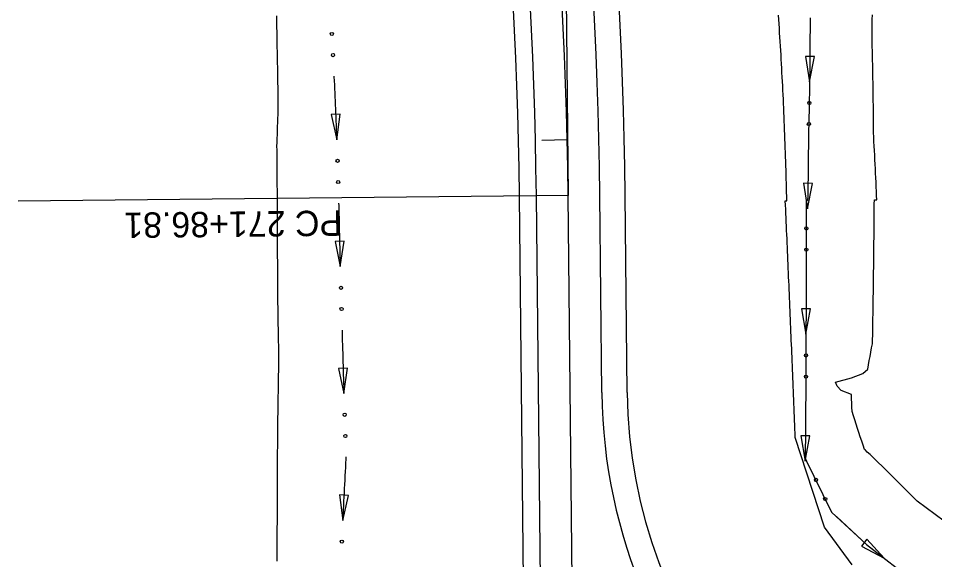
# Model space of a CAD drawing. Extents: x 1611108 to 1749517, y 619561 to 797725.
# Drawn here: x 1713886.8 to 1714103.5, y 759365.7 to 759493.8 of the extents above; entities that cross this region are included whole.
import ezdxf

# ---------------------------------------------------------------- set-up
doc = ezdxf.new("R2010")
doc.units = 0
for name, color, linetype in [('R_Ditch', 7, 'Continuous'), ('R_Horz Alg', 7, 'Continuous'), ('R_Horz Alg Annot', 7, 'Continuous'), ('R_Horz Alg Stationing', 7, 'Continuous'), ('R_Proposed Const Limits', 7, 'Continuous'), ('R_Proposed Road', 7, 'Continuous'), ('R_Proposed_SHLDR', 7, 'Continuous')]:
    doc.layers.add(name, color=color, linetype=linetype)

msp = doc.modelspace()

# ---------------------------------------------------------------- linework, layer by layer
at = {"layer": 'R_Ditch'}
for p, q in [((1714075.03, 759484.75), (1714072.91, 759484.77)), ((1714072.91, 759484.77), (1714073.9, 759478.76)), ((1714073.9, 759478.76), (1714075.03, 759484.75)), ((1713962.91, 759471.09), (1713960.8, 759471.01)), ((1713960.8, 759471.01), (1713962.09, 759465.05)), ((1713962.09, 759465.05), (1713962.91, 759471.09)), ((1714074.57, 759454.71), (1714072.46, 759454.75)), ((1714072.46, 759454.75), (1714073.39, 759448.73)), ((1714073.39, 759448.73), (1714074.57, 759454.71)), ((1713963.82, 759441.05), (1713961.71, 759441)), ((1713961.71, 759441), (1713962.92, 759435.03)), ((1713962.92, 759435.03), (1713963.82, 759441.05)), ((1714074.11, 759425.03), (1714072, 759425.04)), ((1714072, 759425.04), (1714073.04, 759419.04)), ((1714073.04, 759419.04), (1714074.11, 759425.03)), ((1713964.66, 759411.03), (1713962.54, 759410.97)), ((1713962.54, 759410.97), (1713963.78, 759405)), ((1713963.78, 759405), (1713964.66, 759411.03)), ((1714073.97, 759394.99), (1714071.85, 759395.01)), ((1714071.85, 759395.01), (1714072.87, 759389)), ((1714072.87, 759389), (1714073.97, 759394.99)), ((1713964.85, 759380.94), (1713962.74, 759381.04)), ((1713962.74, 759381.04), (1713963.5, 759375)), ((1713963.5, 759375), (1713964.85, 759380.94)), ((1714087.47, 759370.6), (1714086.17, 759368.93)), ((1714091.56, 759366.08), (1714087.47, 759370.6)), ((1714086.17, 759368.93), (1714091.56, 759366.08))]:
    msp.add_line(p, q, dxfattribs=at)
for points in [[(1714084, 759364.54), (1714077.44, 759373.4), (1714070.49, 759394.62), (1714070.45, 759395.62), (1714070.41, 759396.62), (1714070.37, 759397.62), (1714070.33, 759398.62), (1714070.3, 759399.62), (1714070.26, 759400.62), (1714070.22, 759401.62), (1714070.18, 759402.62), (1714070.14, 759403.62), (1714070.1, 759404.62), (1714070.06, 759405.62), (1714070.02, 759406.62), (1714069.99, 759407.62), (1714069.95, 759408.62), (1714069.91, 759409.62), (1714069.87, 759410.62), (1714069.83, 759411.62), (1714069.79, 759412.62), (1714069.75, 759413.62), (1714069.71, 759414.62), (1714069.66, 759415.62), (1714069.62, 759416.61), (1714069.58, 759417.61), (1714069.54, 759418.61), (1714069.5, 759419.61), (1714069.46, 759420.61), (1714069.42, 759421.61), (1714069.38, 759422.61), (1714069.34, 759423.61), (1714069.29, 759424.61), (1714069.25, 759425.61), (1714069.21, 759426.61), (1714069.17, 759427.61), (1714069.13, 759428.61), (1714069.08, 759429.61), (1714069.04, 759430.61), (1714069, 759431.61), (1714068.95, 759432.61), (1714068.91, 759433.61), (1714068.87, 759434.61), (1714068.82, 759435.61), (1714068.78, 759436.61), (1714068.74, 759437.61), (1714068.69, 759438.61), (1714068.65, 759439.61), (1714068.61, 759440.61), (1714068.56, 759441.61), (1714068.52, 759442.6), (1714068.47, 759443.6), (1714068.43, 759444.6), (1714068.38, 759445.6), (1714068.34, 759446.6), (1714068.29, 759447.6), (1714068.25, 759448.6), (1714068.2, 759449.6), (1714068.16, 759450.6), (1714068.16, 759450.61), (1714068.51, 759450.63), (1714068.49, 759451.61), (1714068.47, 759452.61), (1714068.44, 759453.66), (1714068.41, 759454.71), (1714068.39, 759455.76), (1714068.36, 759456.81), (1714068.33, 759457.86), (1714068.3, 759458.91), (1714068.26, 759459.96), (1714068.23, 759461.01), (1714068.2, 759462.06), (1714068.16, 759463.11), (1714068.12, 759464.15), (1714068.08, 759465.2), (1714068.04, 759466.25), (1714068, 759467.3), (1714067.96, 759468.35), (1714067.92, 759469.4), (1714067.88, 759470.45), (1714067.83, 759471.5), (1714067.78, 759472.54), (1714067.74, 759473.59), (1714067.69, 759474.64), (1714067.64, 759475.69), (1714067.59, 759476.74), (1714067.54, 759477.79), (1714067.48, 759478.83), (1714067.43, 759479.88), (1714067.37, 759480.93), (1714067.32, 759481.98), (1714067.26, 759483.02), (1714067.2, 759484.07), (1714067.14, 759485.12), (1714067.08, 759486.17), (1714067.02, 759487.21), (1714066.95, 759488.26), (1714066.89, 759489.31), (1714066.82, 759490.36), (1714066.75, 759491.4), (1714066.69, 759492.45), (1714066.62, 759493.5), (1714066.55, 759494.54)], [(1714074, 759493.85), (1714074, 759492.79), (1714074, 759491.74), (1714074, 759490.68), (1714073.99, 759489.62), (1714073.99, 759488.57), (1714073.98, 759487.51), (1714073.98, 759486.45), (1714073.97, 759485.4), (1714073.96, 759484.34), (1714073.95, 759483.28), (1714073.94, 759482.22), (1714073.93, 759481.17), (1714073.91, 759480.11), (1714073.9, 759479.05), (1714073.88, 759478), (1714073.86, 759476.94), (1714073.85, 759475.89), (1714073.83, 759474.83), (1714073.81, 759473.77), (1714073.78, 759472.72), (1714073.76, 759471.66), (1714073.74, 759470.6), (1714073.71, 759469.55), (1714073.68, 759468.49), (1714073.66, 759467.44), (1714073.63, 759466.38), (1714073.62, 759465.33), (1714073.62, 759464.27), (1714073.61, 759463.22), (1714073.6, 759462.16), (1714073.59, 759461.11), (1714073.58, 759460.05), (1714073.57, 759459), (1714073.56, 759457.94), (1714073.54, 759456.89), (1714073.53, 759455.83), (1714073.51, 759454.78), (1714073.49, 759453.72), (1714073.47, 759452.67), (1714073.45, 759451.66), (1714073.43, 759450.68), (1714073.07, 759450.66), (1714073.07, 759450.65), (1714073.07, 759449.65), (1714073.07, 759448.65), (1714073.08, 759447.65), (1714073.08, 759446.65), (1714073.08, 759445.65), (1714073.08, 759444.65), (1714073.08, 759443.65), (1714073.08, 759442.65), (1714073.08, 759441.65), (1714073.08, 759440.65), (1714073.08, 759439.65), (1714073.08, 759438.65), (1714073.08, 759437.65), (1714073.07, 759436.65), (1714073.07, 759435.65), (1714073.07, 759434.65), (1714073.07, 759433.65), (1714073.07, 759432.65), (1714073.07, 759431.65), (1714073.07, 759430.65), (1714073.06, 759429.65), (1714073.06, 759428.65), (1714073.06, 759427.65), (1714073.06, 759426.65), (1714073.06, 759425.65), (1714073.05, 759424.65), (1714073.05, 759423.65), (1714073.05, 759422.65), (1714073.04, 759421.65), (1714073.04, 759420.65), (1714073.04, 759419.65), (1714073.03, 759418.65), (1714073.03, 759417.65), (1714073.03, 759416.65), (1714073.02, 759415.65), (1714073.02, 759414.65), (1714073.02, 759413.65), (1714073.01, 759412.65), (1714073.01, 759411.65), (1714073, 759410.65), (1714073, 759409.65), (1714072.99, 759408.65), (1714072.99, 759407.65), (1714072.98, 759406.65), (1714072.98, 759405.65), (1714072.97, 759404.65), (1714072.97, 759403.65), (1714072.96, 759402.65), (1714072.95, 759401.65), (1714072.95, 759400.65), (1714072.94, 759399.65), (1714072.94, 759398.65), (1714072.93, 759397.65), (1714072.92, 759396.65), (1714072.92, 759395.65), (1714072.91, 759394.65), (1714072.9, 759393.65), (1714072.89, 759392.65), (1714072.89, 759391.65), (1714072.88, 759390.65), (1714072.87, 759389.65), (1714079.11, 759376.95), (1714087.36, 759369.35), (1714098.95, 759360.33)], [(1714074, 759493.76), (1714074, 759492.79), (1714074, 759491.74), (1714074, 759490.68), (1714073.99, 759489.62), (1714073.99, 759488.57), (1714073.98, 759487.51), (1714073.98, 759486.45), (1714073.97, 759485.4), (1714073.96, 759484.34), (1714073.95, 759483.28), (1714073.94, 759482.22), (1714073.93, 759481.17), (1714073.91, 759480.11), (1714073.9, 759479.05), (1714073.89, 759478.76)], [(1713961.44, 759480.08), (1713961.44, 759480.04)], [(1713961.44, 759480.04), (1713961.44, 759479.91), (1713961.49, 759478.97), (1713961.54, 759478.02), (1713961.58, 759477.07), (1713961.63, 759476.13), (1713961.67, 759475.18), (1713961.71, 759474.23), (1713961.75, 759473.29), (1713961.79, 759472.34), (1713961.83, 759471.39), (1713961.87, 759470.45), (1713961.91, 759469.5), (1713961.95, 759468.55), (1713961.99, 759467.61), (1713962.02, 759466.66), (1713962.06, 759465.71), (1713962.08, 759465.05)], [(1714073.61, 759463.73), (1714073.61, 759463.22), (1714073.6, 759462.16), (1714073.59, 759461.11), (1714073.58, 759460.05), (1714073.57, 759459), (1714073.56, 759457.94), (1714073.54, 759456.89), (1714073.53, 759455.83), (1714073.51, 759454.78), (1714073.49, 759453.72), (1714073.47, 759452.67), (1714073.45, 759451.66), (1714073.43, 759450.68), (1714073.07, 759450.66), (1714073.07, 759450.65), (1714073.07, 759449.65), (1714073.07, 759449.07)], [(1714073.61, 759463.76), (1714073.61, 759463.73)], [(1713962.54, 759450.06), (1713962.54, 759450.02)], [(1713962.54, 759450.02), (1713962.55, 759449.51), (1713962.58, 759448.51), (1713962.6, 759447.51), (1713962.63, 759446.51), (1713962.65, 759445.51), (1713962.68, 759444.51), (1713962.7, 759443.51), (1713962.73, 759442.51), (1713962.75, 759441.51), (1713962.78, 759440.51), (1713962.8, 759439.51), (1713962.83, 759438.51), (1713962.86, 759437.51), (1713962.88, 759436.51), (1713962.91, 759435.51), (1713962.92, 759435.03)], [(1714073.07, 759434.04), (1714073.07, 759433.65), (1714073.07, 759432.65), (1714073.07, 759431.65), (1714073.07, 759430.65), (1714073.06, 759429.65), (1714073.06, 759428.65), (1714073.06, 759427.65), (1714073.06, 759426.65), (1714073.06, 759425.65), (1714073.05, 759424.65), (1714073.05, 759423.65), (1714073.05, 759422.65), (1714073.04, 759421.65), (1714073.04, 759420.65), (1714073.04, 759419.65), (1714073.04, 759419.04)], [(1714073.07, 759434.07), (1714073.07, 759434.04)], [(1713963.34, 759420.03), (1713963.34, 759420)], [(1713963.34, 759419.99), (1713963.35, 759419.52), (1713963.38, 759418.52), (1713963.41, 759417.52), (1713963.44, 759416.52), (1713963.47, 759415.52), (1713963.5, 759414.52), (1713963.53, 759413.52), (1713963.56, 759412.52), (1713963.59, 759411.52), (1713963.62, 759410.52), (1713963.65, 759409.52), (1713963.68, 759408.52), (1713963.71, 759407.52), (1713963.74, 759406.52), (1713963.77, 759405.52), (1713963.78, 759405)], [(1714072.97, 759404), (1714072.97, 759403.65), (1714072.96, 759402.65), (1714072.95, 759401.65), (1714072.95, 759400.65), (1714072.94, 759399.65), (1714072.94, 759398.65), (1714072.93, 759397.65), (1714072.92, 759396.65), (1714072.92, 759395.65), (1714072.91, 759394.65), (1714072.9, 759393.65), (1714072.89, 759392.65), (1714072.89, 759391.65), (1714072.88, 759390.65), (1714072.87, 759389.65), (1714073.16, 759389.07)], [(1714072.97, 759404.04), (1714072.97, 759404)], [(1713964.25, 759389.98), (1713964.23, 759389.53), (1713964.18, 759388.53), (1713964.13, 759387.54), (1713964.08, 759386.54), (1713964.03, 759385.54), (1713963.98, 759384.54), (1713963.93, 759383.54), (1713963.87, 759382.54), (1713963.82, 759381.54), (1713963.77, 759380.54), (1713963.72, 759379.54), (1713963.68, 759378.54), (1713963.63, 759377.55), (1713963.58, 759376.55), (1713963.53, 759375.55), (1713963.5, 759375)], [(1713964.25, 759390.02), (1713964.25, 759389.98)], [(1714080.21, 759375.93), (1714080.24, 759375.91)], [(1714080.24, 759375.91), (1714087.36, 759369.35), (1714091.56, 759366.08)]]:
    msp.add_lwpolyline(points, dxfattribs=at)
for centre in [(1713960.94, 759490.06), (1713961.22, 759485.06), (1714073.84, 759473.76), (1714073.73, 759468.75), (1713962.29, 759460.05), (1713962.44, 759455.04), (1714073.11, 759444.07), (1714073.11, 759439.06), (1713963.09, 759430.02), (1713963.23, 759425.02), (1714073.05, 759414.03), (1714073.03, 759409.02), (1713963.98, 759400), (1713964.14, 759394.99), (1714075.4, 759384.59), (1714077.6, 759380.09), (1713963.29, 759370)]:
    msp.add_circle(centre, 0.375, dxfattribs=at)
at = {"layer": 'R_Horz Alg'}
msp.add_line((1714018.73, 759265.08), (1714016.8, 759451.89), dxfattribs=at)
msp.add_arc((1712975.11, 759441.13), 1041.74, 0.59167, 23.75, dxfattribs=at)
at = {"layer": 'R_Horz Alg Annot'}
msp.add_line((1714014.59, 759665.32), (1714016.8, 759451.89), dxfattribs=at)
msp.add_lwpolyline([(1714016.8, 759451.89), (1713886.8, 759450.54)], dxfattribs=at)
at = {"layer": 'R_Horz Alg Stationing'}
msp.add_lwpolyline([(1714010.58, 759464.93), (1714016.58, 759465.07)], dxfattribs=at)
at = {"layer": 'R_Proposed Const Limits'}
for points in [[(1713948.02, 759365.36), (1713948.02, 759366.36), (1713948.03, 759367.36), (1713948.03, 759368.36), (1713948.03, 759369.36), (1713948.03, 759370.36), (1713948.04, 759371.36), (1713948.04, 759372.36), (1713948.04, 759373.36), (1713948.05, 759374.36), (1713948.05, 759375.36), (1713948.05, 759376.36), (1713948.06, 759377.36), (1713948.06, 759378.36), (1713948.06, 759379.36), (1713948.07, 759380.36), (1713948.07, 759381.36), (1713948.08, 759382.36), (1713948.08, 759383.36), (1713948.09, 759384.36), (1713948.09, 759385.36), (1713948.1, 759386.36), (1713948.1, 759387.36), (1713948.11, 759388.36), (1713948.11, 759389.36), (1713948.12, 759390.36), (1713948.12, 759391.36), (1713948.13, 759392.36), (1713948.14, 759393.36), (1713948.14, 759394.36), (1713948.15, 759395.36), (1713948.16, 759396.36), (1713948.17, 759397.36), (1713948.19, 759398.36), (1713948.2, 759399.36), (1713948.22, 759400.36), (1713948.23, 759401.36), (1713948.25, 759402.36), (1713948.26, 759403.36), (1713948.28, 759404.36), (1713948.3, 759405.36), (1713948.31, 759406.36), (1713948.33, 759407.36), (1713948.34, 759408.36), (1713948.36, 759409.36), (1713948.38, 759410.36), (1713948.39, 759411.36), (1713948.41, 759412.36), (1713948.43, 759413.36), (1713948.43, 759414.36), (1713948.41, 759415.36), (1713948.38, 759416.36), (1713948.36, 759417.36), (1713948.34, 759418.36), (1713948.32, 759419.36), (1713948.3, 759420.36), (1713948.28, 759421.36), (1713948.25, 759422.36), (1713948.23, 759423.36), (1713948.22, 759424.36), (1713948.21, 759425.36), (1713948.2, 759426.36), (1713948.19, 759427.36), (1713948.18, 759428.36), (1713948.18, 759429.36), (1713948.17, 759430.36), (1713948.16, 759431.36), (1713948.16, 759432.36), (1713948.15, 759433.36), (1713948.14, 759434.36), (1713948.14, 759435.36), (1713948.13, 759436.36), (1713948.12, 759437.36), (1713948.12, 759438.36), (1713948.11, 759439.36), (1713948.11, 759440.36), (1713948.1, 759441.36), (1713948.1, 759442.36), (1713948.09, 759443.36), (1713948.09, 759444.36), (1713948.08, 759445.36), (1713948.08, 759446.36), (1713948.07, 759447.36), (1713948.07, 759448.36), (1713948.06, 759449.36), (1713948.06, 759450.36), (1713948.06, 759451.35), (1713948.05, 759452.28), (1713948.05, 759453.22), (1713948.04, 759454.15), (1713948.04, 759455.09), (1713948.03, 759456.02), (1713948.03, 759456.95), (1713948.02, 759457.89), (1713948.01, 759458.82), (1713948, 759459.76), (1713947.99, 759460.69), (1713947.98, 759461.62), (1713947.97, 759462.56), (1713947.96, 759463.49), (1713947.97, 759464.43), (1713948.01, 759465.36), (1713948.05, 759466.3), (1713948.09, 759467.23), (1713948.12, 759468.17), (1713948.16, 759469.1), (1713948.2, 759470.04), (1713948.23, 759470.98), (1713948.27, 759471.91), (1713948.27, 759472.85), (1713948.26, 759473.78), (1713948.25, 759474.72), (1713948.24, 759475.65), (1713948.23, 759476.59), (1713948.22, 759477.52), (1713948.2, 759478.46), (1713948.19, 759479.39), (1713948.17, 759480.33), (1713948.16, 759481.26), (1713948.14, 759482.2), (1713948.12, 759483.13), (1713948.1, 759484.07), (1713948.08, 759485), (1713948.06, 759485.94), (1713948.04, 759486.87), (1713948.02, 759487.81), (1713948, 759488.74), (1713947.98, 759489.68), (1713947.97, 759490.61), (1713947.95, 759491.55), (1713947.94, 759492.48), (1713947.92, 759493.42), (1713947.9, 759494.36)], [(1714105.7, 759374.84), (1714099.3, 759379.56), (1714091.59, 759387.32), (1714089.59, 759389.25), (1714088.23, 759390.62), (1714087.52, 759391.15), (1714087.1, 759391.6), (1714086.87, 759391.79), (1714086.54, 759392.79), (1714086.22, 759393.78), (1714085.89, 759394.78), (1714085.56, 759395.78), (1714085.24, 759396.78), (1714084.91, 759397.77), (1714084.58, 759398.77), (1714084.26, 759399.77), (1714083.93, 759400.76), (1714083.89, 759401.76), (1714083.87, 759402.76), (1714083.84, 759403.76), (1714083.82, 759404.76), (1714081.39, 759405.74), (1714080.43, 759406.73), (1714080.04, 759407.72), (1714083.82, 759408.76), (1714086.49, 759409.79), (1714087.63, 759410.8), (1714087.82, 759411.8), (1714088.01, 759412.8), (1714088.19, 759413.81), (1714088.38, 759414.81), (1714088.57, 759415.81), (1714088.76, 759416.81), (1714088.8, 759417.81), (1714088.82, 759418.81), (1714088.83, 759419.81), (1714088.85, 759420.81), (1714088.87, 759421.81), (1714088.88, 759422.81), (1714088.9, 759423.81), (1714088.91, 759424.81), (1714088.93, 759425.81), (1714088.94, 759426.81), (1714088.95, 759427.82), (1714088.97, 759428.82), (1714088.98, 759429.82), (1714089, 759430.82), (1714089.01, 759431.82), (1714089.02, 759432.82), (1714089.03, 759433.82), (1714089.05, 759434.82), (1714089.06, 759435.82), (1714089.07, 759436.82), (1714089.08, 759437.82), (1714089.1, 759438.82), (1714089.11, 759439.82), (1714089.12, 759440.82), (1714089.13, 759441.82), (1714089.14, 759442.82), (1714089.15, 759443.82), (1714089.16, 759444.82), (1714089.17, 759445.82), (1714089.18, 759446.82), (1714089.19, 759447.82), (1714089.2, 759448.82), (1714089.2, 759449.82), (1714089.21, 759450.82), (1714089.21, 759450.83), (1714089.76, 759450.84), (1714089.74, 759451.82), (1714089.7, 759452.84), (1714089.66, 759453.91), (1714089.61, 759454.98), (1714089.56, 759456.05), (1714089.51, 759457.11), (1714089.46, 759458.18), (1714089.41, 759459.25), (1714089.35, 759460.32), (1714089.3, 759461.39), (1714089.24, 759462.46), (1714089.18, 759463.53), (1714089.12, 759464.6), (1714089.06, 759465.67), (1714089, 759466.73), (1714089, 759467.8), (1714088.99, 759468.87), (1714088.99, 759469.94), (1714088.98, 759471.01), (1714088.98, 759472.08), (1714088.97, 759473.15), (1714088.96, 759474.22), (1714088.95, 759475.29), (1714088.93, 759476.36), (1714088.92, 759477.43), (1714088.9, 759478.5), (1714088.88, 759479.57), (1714088.86, 759480.64), (1714088.84, 759481.71), (1714088.82, 759482.78), (1714088.8, 759483.85), (1714088.77, 759484.92), (1714088.75, 759485.99), (1714088.72, 759487.06), (1714088.69, 759488.13), (1714088.68, 759489.2), (1714088.7, 759490.27), (1714088.71, 759491.34), (1714088.72, 759492.42), (1714088.73, 759493.49), (1714088.74, 759494.56)]]:
    msp.add_lwpolyline(points, dxfattribs=at)
at = {"layer": 'R_Proposed Road'}
for p, q in [((1714010.39, 759346), (1714009.3, 759451.81)), ((1714024.78, 759405.24), (1714024.3, 759451.96))]:
    msp.add_line(p, q, dxfattribs=at)
for centre, radius, start, end in [((1712975.11, 759441.13), 1049.24, 0.59167, 23.75), ((1712975.11, 759441.13), 1034.24, 0.59167, 23.75), ((1714149.77, 759406.53), 125, 180.5917, 269.3186)]:
    msp.add_arc(centre, radius, start, end, dxfattribs=at)
at = {"layer": 'R_Proposed_SHLDR'}
for p, q in [((1714006.39, 759345.96), (1714005.3, 759451.77)), ((1714030.78, 759405.3), (1714030.3, 759452.02))]:
    msp.add_line(p, q, dxfattribs=at)
for centre, radius, start, end in [((1712975.11, 759441.13), 1055.24, 0.59167, 23.75), ((1712975.11, 759441.13), 1030.24, 0.59167, 23.75), ((1714149.77, 759406.53), 119, 180.5917, 258.7915)]:
    msp.add_arc(centre, radius, start, end, dxfattribs=at)

# ---------------------------------------------------------------- texts
at = {"layer": 'R_Horz Alg Annot'}
msp.add_text('PC 271+86.81', height=6, rotation=180.5917, dxfattribs=at).set_placement((1713963.33, 759448.33))

doc.saveas('drawing.dxf')
